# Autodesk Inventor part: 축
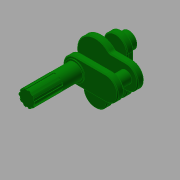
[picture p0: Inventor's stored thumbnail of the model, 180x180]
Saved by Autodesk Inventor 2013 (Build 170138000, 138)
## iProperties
Created: 2017-05
Part Number: 축
Material: 강철, 연강
Document SubType Name: Modeling
Designer: mduedu
Density: 7.86 g/cm^3
Mass: 650.749 g
Surface Area: 241.48 cm^2
Volume: 82.7924 cm^3
Author: mduedu
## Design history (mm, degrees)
sketch "스케치1"
  geometry: L1 (-38, 15)-(-17.436, 15); L2 (-38, -15)-(-17.436, -15); L3 (-15, -38)-(-15, -17.436); L4 (15, -38)-(15, -17.436); A1 r 23 centre (0, 0) between (-17.436, 15) and (-17.436, -15); A2 r 15 centre (-38, 0) between (-38, 15) and (-38, -15); A3 r 15 centre (0, -38) between (-15, -38) and (15, -38); 1 further point
  constraints: 8 end point, 8 point on circle, 4 tangent, 3 centre point, 2 horizontal, 2 vertical, 1 coincident, 1 horizontal alignment, 1 vertical alignment
  dimensions: "d0" = 46 diameter of A1; "d1" = 30 diameter of A2; "d2" = 30 diameter of A3 (= d1); "d3" = 38 distance of point (0, 0) A2.centre; "d4" = 38 distance of A3.centre point (0, 0)
extrude "돌출1" new body sketch "스케치1" distance "d5" = 8; taper "d6" = 0 deg
fillet "모깎기1" dims "d7" = 3
sketch "스케치2"
  geometry: C1 r 7.5 at (0, -38); A1 r 15 centre (0, -38) between (-15, -38) and (15, -38) reference; 1 further point
  constraints: 1 centre point, 1 coincident
  dimensions: "d8" = 15 diameter of C1
extrude "돌출2" join sketch "스케치2" distance "d9" = 17; taper "d10" = 0 deg
sketch "스케치3"
  geometry: L1 (-15, 0)-(-15, 38); L2 (15, 0)-(15, 38); C1 r 7.5 at (0, 0) reference; A1 r 15 centre (0, 0) between (-15, 0) and (15, 0); A2 r 15 centre (0, 38) between (-15, 38) and (15, 38); 1 further point
  constraints: 4 end point, 4 point on circle, 4 tangent, 2 centre point, 2 coincident
  dimensions: "d11" = 30 diameter of A1; "d12" = 30 diameter of A2 (= d11)
extrude "돌출3" join sketch "스케치3" distance "d13" = 8; taper "d14" = 0 deg
sketch "스케치4"
  geometry: C1 r 12 at (0, 38); A1 r 15 centre (0, 38) between (15, 38) and (-15, 38) reference; 1 further point
  constraints: 1 centre point, 1 coincident
  dimensions: "d15" = 24 diameter of C1
extrude "돌출4" join sketch "스케치4" distance "d16" = 1; taper "d17" = 0 deg
sketch "스케치5"
  geometry: C1 r 10 at (0, 0); 1 further point
  constraints: 1 centre point, 1 coincident
  dimensions: "d18" = 20 diameter of C1
extrude "돌출5" join sketch "스케치5" distance "d19" = 8; taper "d20" = 0 deg
sketch "스케치6"
  geometry: C1 r 7.5 at (38, 0); A1 r 15 centre (38, 0) between (38, -15) and (38, 15) reference; 1 further point
  constraints: 1 centre point, 1 coincident
  dimensions: "d21" = 15 diameter of C1
extrude "돌출6" join sketch "스케치6" distance "d22" = 17; taper "d23" = 0 deg
sketch "스케치7"
  geometry: L1 (-38, 15)-(0, 15); L2 (-38, -15)-(0, -15); C1 r 7.5 at (0, 0) reference; A1 r 15 centre (0, 0) between (0, 15) and (0, -15); A2 r 15 centre (-38, 0) between (-38, 15) and (-38, -15); 1 further point
  constraints: 4 end point, 4 point on circle, 4 tangent, 2 centre point, 2 coincident
  dimensions: "d24" = 30 diameter of A1; "d25" = 30 diameter of A2 (= d24)
extrude "돌출7" join sketch "스케치7" distance "d26" = 8; taper "d27" = 0 deg
sketch "스케치8"
  geometry: C1 r 12 at (-38, 0); 1 further point
  constraints: 1 centre point, 1 coincident
  dimensions: "d28" = 24 diameter of C1
extrude "돌출8" join sketch "스케치8" distance "d29" = 1; taper "d30" = 0 deg
sketch "스케치9"
  geometry: C1 r 10 at (0, 0); 1 further point
  constraints: 1 centre point, 1 coincident
  dimensions: "d31" = 20 diameter of C1
extrude "돌출9" join sketch "스케치9" distance "d32" = 24; taper "d33" = 0 deg
sketch "스케치10"
  geometry: L1 (1.5, 9.887)-(1.5, 8.887); L2 (1.5, 8.887)-(-1.5, 8.887); L3 (-1.5, 8.887)-(-1.5, 9.887); L4 (-4.598, 8.88)-(-4.01, 8.071); L5 (-4.01, 8.071)-(-6.437, 6.308); L6 (-6.437, 6.308)-(-7.025, 7.117); L7 (-8.939, 4.482)-(-7.988, 4.173); L8 (-7.988, 4.173)-(-8.915, 1.32); L9 (-8.915, 1.32)-(-9.866, 1.629); L10 (-9.866, -1.629)-(-8.915, -1.32); L11 (-8.915, -1.32)-(-7.988, -4.173); L12 (-7.988, -4.173)-(-8.939, -4.482); L13 (-7.025, -7.117)-(-6.437, -6.308); L14 (-6.437, -6.308)-(-4.01, -8.071); L15 (-4.01, -8.071)-(-4.598, -8.88); L16 (-1.5, -9.887)-(-1.5, -8.887); L17 (-1.5, -8.887)-(1.5, -8.887); L18 (1.5, -8.887)-(1.5, -9.887); L19 (4.598, -8.88)-(4.01, -8.071); L20 (4.01, -8.071)-(6.437, -6.308); L21 (6.437, -6.308)-(7.025, -7.117); L22 (8.939, -4.482)-(7.988, -4.173); L23 (7.988, -4.173)-(8.915, -1.32); L24 (8.915, -1.32)-(9.866, -1.629); L25 (9.866, 1.629)-(8.915, 1.32); L26 (8.915, 1.32)-(7.988, 4.173); L27 (7.988, 4.173)-(8.939, 4.482); L28 (7.025, 7.117)-(6.437, 6.308); L29 (6.437, 6.308)-(4.01, 8.071); L30 (4.01, 8.071)-(4.598, 8.88); A1 r 10 centre (0, 0) between (1.5, 9.887) and (-1.5, 9.887); A2 r 10 centre (0, 0) between (-4.598, 8.88) and (-7.025, 7.117); A3 r 10 centre (0, 0) between (-8.939, 4.482) and (-9.866, 1.629); A4 r 10 centre (0, 0) between (-9.866, -1.629) and (-8.939, -4.482); A5 r 10 centre (0, 0) between (-7.025, -7.117) and (-4.598, -8.88); A6 r 10 centre (0, 0) between (-1.5, -9.887) and (1.5, -9.887); A7 r 10 centre (0, 0) between (4.598, -8.88) and (7.025, -7.117); A8 r 10 centre (0, 0) between (8.939, -4.482) and (9.866, -1.629); A9 r 10 centre (0, 0) between (9.866, 1.629) and (8.939, 4.482); A10 r 10 centre (0, 0) between (7.025, 7.117) and (4.598, 8.88); 13 further points
  constraints: 60 end point, 20 point on circle, 10 centre point, 3 coincident, 1 horizontal, 1 midpoint, 1 parallel, 1 vertical, 1 vertical alignment, 103 other
  dimensions: "d37" = 3 distance of L1.end L2.end; "d39" = 1 distance of L2.end L3.end; "d42" = 360 deg dimension on A1.centre L1.start (derived)
extrude "돌출10" join sketch "스케치10" distance "d44" = 35; taper "d45" = 0 deg
chamfer "모따기1" distance "d46" = 1; stored, may be unused: second distance "d47" = 2, angle "d48" = 45 deg
node "솔리드1"
node "투영된 루프1"
node "투영된 루프2"
node "투영된 루프3"
